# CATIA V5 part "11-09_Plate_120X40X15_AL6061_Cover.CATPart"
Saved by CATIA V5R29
Part number: 11-09_Plate_120X40X15_AL6061
Bounding box of the stored display mesh (mm): x -60 to 60, y -20 to 20, z 0 to 15
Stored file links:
  C:\Users\CDL\Desktop\PostConveyor\PostConveyor_Part\11-09_Plate_120X40X15_AL6061.CATPart
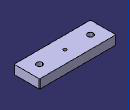
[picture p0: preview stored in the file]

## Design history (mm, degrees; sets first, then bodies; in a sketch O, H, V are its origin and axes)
Body1 (main body)
  Sketch1 on xy-plane, origin (0, 0, 0), H (1, 0, 0), V (0, 1, 0)
    line L1 (60, 20) -> (60, -20)
    line L2 (60, -20) -> (-60, -20)
    line L3 (-60, -20) -> (-60, 20)
    line L4 (-60, 20) -> (60, 20)
    length L1 = 40
    length L4 = 120
    vertical: L1 V, L3 V
    horizontal: L2 H, L4 H
    equidistance: L1 L3 O, L2 L4 O
  Pad1: profile Sketch1, direction (0, 0, 1), length 15
  Sketch2 on start face of Pad1, origin (-39.1075, 0.7725, 0), H (1, 0, 0), V (0, -1, 0)
    point P1 (-0.8925, 0.7725)
    reference projected line E1 (-20.8925, 20.7725) -> (99.1075, 20.7725) from edge [start face of Pad1 | face of Pad1 from Sketch1.L2]
    reference projected line E2 (-20.8925, -19.2275) -> (-20.8925, 20.7725) from edge [start face of Pad1 | face of Pad1 from Sketch1.L3]
    distance P1 E1 = 20
    distance P1 E2 = 20
  Hole1: placed by Sketch2, at (-40, 0, 0) direction (0, 0, 1), diameter 9, through (limit type 3), counterbore diameter 14, counterbore depth 8.6
  Mirror1: of Hole1, about yz-plane
  Sketch3 on start face of Pad1, origin (0.1459, 1.8067, 0), H (1, 0, 0), V (0, -1, 0)
    point P1 (-0.1459, 1.8067)
    reference intersected line E1 through (0, 1.8067) direction (1, 0) from zx-plane
    reference intersected line E2 through (-0.1459, 0) direction (0, 1) from yz-plane
    coincidence: P1 E1, P1 E2
  Hole2: placed by Sketch3, at (0, 0, 0) direction (0, 0, 1), diameter 4.917, through (limit type 3), threaded "M6", thread diameter 6, thread depth 15, pitch 1
  Chamfer1: length 1, angle 45, on edge [start face of Pad1 | face of Pad1 from Sketch1.L4]; edge [start face of Pad1 | face of Pad1 from Sketch1.L3]; edge [start face of Pad1 | face of Pad1 from Sketch1.L2]; edge [start face of Pad1 | face of Pad1 from Sketch1.L1]; edge [face of Pad1 from Sketch1.L4 | face of Pad1 from Sketch1.L1]; edge [face of Pad1 from Sketch1.L1 | face of Pad1 from Sketch1.L2]; edge [face of Pad1 from Sketch1.L3 | face of Pad1 from Sketch1.L4]; edge [face of Pad1 from Sketch1.L2 | face of Pad1 from Sketch1.L3]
